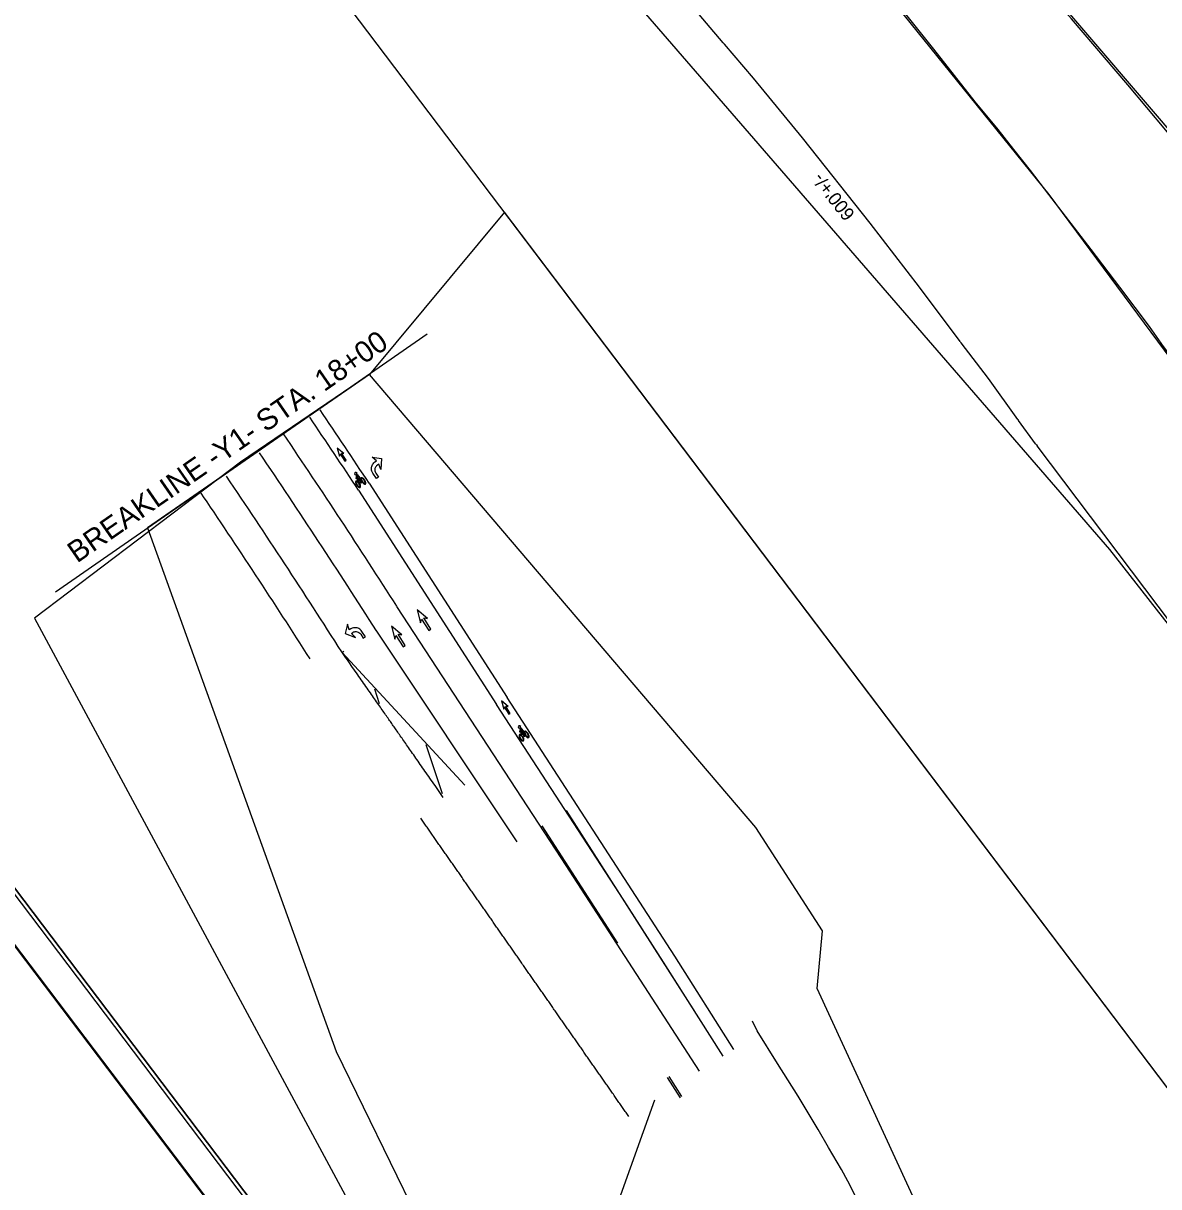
# Model space of a CAD drawing. Extents: x 2046295 to 2051060, y 758814 to 763808.
# Drawn here: x 2046525.7 to 2046973.6, y 759223.6 to 759682.5 of the extents above; entities that cross this region are included whole.
import ezdxf

# ---------------------------------------------------------------- set-up
doc = ezdxf.new("R2010")
doc.units = 0
for name, color, linetype in [('Default', 7, 'Continuous'), ('Exist Mkg 3ft Min Skp 9ft White', 7, 'Continuous'), ('Exist Mkg Skp Wht', 7, 'Continuous'), ('Exist Mkg Solid Double Yellow', 7, 'Continuous'), ('Exist Mkg Solid White Lane Line', 7, 'Continuous'), ('Exist Mkg Solid Yellow Diagonals', 7, 'Continuous'), ('Matchline', 7, 'Continuous'), ('Matchline Text', 7, 'Continuous'), ('Prop Conc 1ft 6in Curb and Gutter', 7, 'Continuous'), ('Prop DSN Text', 7, 'Continuous'), ('Prop EOT', 7, 'Continuous'), ('Prop Lane Lines', 7, 'Continuous'), ('Scratch_Level_0', 7, 'Continuous'), ('Scratch_Level_3', 7, 'Continuous'), ('Sheet Block Revision CELL', 7, 'Continuous'), ('Sheet Clip Boundary CELL', 7, 'Continuous'), ('Sheet Cutting Line CELL', 7, 'Continuous'), ('Sheet Plan CELL', 7, 'Continuous'), ('Sheet Plot Border Inside CELL', 7, 'Continuous'), ('Sheet Plot Border Outside CELL', 7, 'Continuous')]:
    doc.layers.add(name, color=color, linetype=linetype)

msp = doc.modelspace()

# ---------------------------------------------------------------- linework, layer by layer
at = {"layer": 'Default'}
msp.add_line((2046651.81, 759434.8), (2046652, 759434.52), dxfattribs=at)
at = {"layer": 'Exist Mkg 3ft Min Skp 9ft White'}
msp.add_line((2046720.53, 759359.65), (2046664.94, 759443.16), dxfattribs=at)
at = {"layer": 'Exist Mkg Skp Wht'}
for p, q in [((2046656.48, 759504.48), (2046656.6, 759504.57)), ((2046656.48, 759504.48), (2046656.6, 759504.57)), ((2046657.09, 759502.93), (2046657.26, 759504.26)), ((2046657.26, 759502.67), (2046657.09, 759502.93)), ((2046657.26, 759504.26), (2046657.47, 759504.52)), ((2046657.45, 759504.04), (2046657.26, 759502.67)), ((2046657.28, 759505.03), (2046657.41, 759505.12)), ((2046657.28, 759505.03), (2046657.41, 759505.12)), ((2046658.11, 759503.17), (2046657.45, 759504.04)), ((2046657.47, 759504.52), (2046658.49, 759503.19)), ((2046657.56, 759502.32), (2046658.11, 759503.17)), ((2046658.29, 759503.01), (2046657.86, 759502.36)), ((2046658.79, 759501.09), (2046658.29, 759503.01)), ((2046658.49, 759503.19), (2046659.02, 759501.15)), ((2046657.48, 759500.4), (2046657.28, 759500.27)), ((2046657.48, 759500.4), (2046657.28, 759500.27)), ((2046658.17, 759501.74), (2046657.56, 759502.32)), ((2046657.86, 759502.36), (2046658.33, 759501.91)), ((2046658.35, 759501), (2046658.15, 759500.86)), ((2046658.35, 759501), (2046658.15, 759500.86)), ((2046658.33, 759501.91), (2046658.17, 759501.74)), ((2046659.02, 759501.15), (2046658.8, 759501.06)), ((2046659.5, 759501.77), (2046659.3, 759501.64)), ((2046659.5, 759501.77), (2046659.3, 759501.64)), ((2046660.38, 759502.37), (2046660.18, 759502.23)), ((2046660.38, 759502.37), (2046660.18, 759502.23)), ((2046721.03, 759404.57), (2046721.16, 759404.66)), ((2046721.03, 759404.57), (2046721.16, 759404.66)), ((2046721.6, 759403), (2046721.81, 759404.33)), ((2046721.76, 759402.74), (2046721.6, 759403)), ((2046721.99, 759404.1), (2046721.76, 759402.74)), ((2046721.81, 759404.33), (2046722.02, 759404.58)), ((2046721.85, 759405.1), (2046721.98, 759405.18)), ((2046721.85, 759405.1), (2046721.98, 759405.18)), ((2046722.63, 759403.22), (2046721.99, 759404.1)), ((2046722.02, 759404.58), (2046723, 759403.23)), ((2046722.05, 759402.38), (2046722.63, 759403.22)), ((2046722.64, 759401.79), (2046722.05, 759402.38)), ((2046722.8, 759403.06), (2046722.36, 759402.41)), ((2046722.36, 759402.41), (2046722.81, 759401.95)), ((2046722.81, 759401.95), (2046722.64, 759401.79)), ((2046723.25, 759401.11), (2046722.8, 759403.06)), ((2046723, 759403.23), (2046723.48, 759401.17)), ((2046723.98, 759401.78), (2046723.78, 759401.65)), ((2046723.98, 759401.78), (2046723.78, 759401.65)), ((2046724.87, 759402.35), (2046724.67, 759402.22)), ((2046724.87, 759402.35), (2046724.67, 759402.22)), ((2046721.92, 759400.47), (2046721.71, 759400.34)), ((2046721.92, 759400.47), (2046721.71, 759400.34)), ((2046722.81, 759401.04), (2046722.61, 759400.91)), ((2046722.81, 759401.04), (2046722.61, 759400.91)), ((2046723.48, 759401.17), (2046723.26, 759401.09))]:
    msp.add_line(p, q, dxfattribs=at)
for points in [[(2046650.5, 759511.7), (2046650.71, 759512.61), (2046652.62, 759509.8), (2046653.15, 759510.16), (2046651.24, 759512.97), (2046652.17, 759512.83), (2046649.52, 759514.94)], [(2046650.5, 759511.7), (2046650.71, 759512.61), (2046652.62, 759509.8), (2046653.15, 759510.16), (2046651.24, 759512.97), (2046652.17, 759512.83), (2046649.52, 759514.94)], [(2046665.84, 759503.51), (2046665.01, 759502.96), (2046663.58, 759505.11), (2046663.34, 759505.52), (2046663.19, 759505.86), (2046663.08, 759506.26), (2046663.04, 759506.63), (2046663.05, 759506.94), (2046663.1, 759507.37), (2046663.19, 759507.69), (2046663.31, 759508.05), (2046663.51, 759508.47), (2046663.7, 759508.74), (2046663.99, 759509.08), (2046664.43, 759509.47), (2046665.1, 759509.91), (2046663.31, 759511.42), (2046667.1, 759510.83), (2046666.8, 759506.44), (2046665.98, 759508.59), (2046665.42, 759508.22), (2046665.12, 759508), (2046664.88, 759507.73), (2046664.73, 759507.48), (2046664.55, 759507.12), (2046664.46, 759506.83), (2046664.42, 759506.41), (2046664.47, 759505.99), (2046664.56, 759505.59), (2046664.78, 759505.11)], [(2046665.84, 759503.51), (2046665.01, 759502.96), (2046663.58, 759505.11), (2046663.34, 759505.52), (2046663.19, 759505.86), (2046663.08, 759506.26), (2046663.04, 759506.63), (2046663.05, 759506.94), (2046663.1, 759507.37), (2046663.19, 759507.69), (2046663.31, 759508.05), (2046663.51, 759508.47), (2046663.7, 759508.74), (2046663.99, 759509.08), (2046664.43, 759509.47), (2046665.1, 759509.91), (2046663.31, 759511.42), (2046667.1, 759510.83), (2046666.8, 759506.44), (2046665.98, 759508.59), (2046665.42, 759508.22), (2046665.12, 759508), (2046664.88, 759507.73), (2046664.73, 759507.48), (2046664.55, 759507.12), (2046664.46, 759506.83), (2046664.42, 759506.41), (2046664.47, 759505.99), (2046664.56, 759505.59), (2046664.78, 759505.11)], [(2046682.47, 759446.07), (2046682.85, 759447.5), (2046685.71, 759443), (2046686.56, 759443.53), (2046683.69, 759448.03), (2046685.14, 759447.77), (2046681.08, 759451.21)], [(2046682.47, 759446.07), (2046682.85, 759447.5), (2046685.71, 759443), (2046686.56, 759443.53), (2046683.69, 759448.03), (2046685.14, 759447.77), (2046681.08, 759451.21)], [(2046659.86, 759439.92), (2046660.7, 759440.46), (2046659.31, 759442.64), (2046659.03, 759443.03), (2046658.79, 759443.3), (2046658.47, 759443.56), (2046658.14, 759443.75), (2046657.86, 759443.87), (2046657.45, 759444), (2046657.12, 759444.05), (2046656.74, 759444.09), (2046656.28, 759444.07), (2046655.94, 759444.01), (2046655.52, 759443.89), (2046654.98, 759443.64), (2046654.31, 759443.21), (2046653.66, 759445.46), (2046652.66, 759441.76), (2046656.79, 759440.24), (2046655.16, 759441.87), (2046655.72, 759442.23), (2046656.05, 759442.41), (2046656.39, 759442.52), (2046656.68, 759442.56), (2046657.08, 759442.57), (2046657.39, 759442.54), (2046657.79, 759442.4), (2046658.15, 759442.19), (2046658.47, 759441.94), (2046658.83, 759441.54)], [(2046659.86, 759439.92), (2046660.7, 759440.46), (2046659.31, 759442.64), (2046659.03, 759443.03), (2046658.79, 759443.3), (2046658.47, 759443.56), (2046658.14, 759443.75), (2046657.86, 759443.87), (2046657.45, 759444), (2046657.12, 759444.05), (2046656.74, 759444.08), (2046656.28, 759444.07), (2046655.94, 759444.01), (2046655.52, 759443.89), (2046654.98, 759443.64), (2046654.31, 759443.21), (2046653.66, 759445.46), (2046652.66, 759441.76), (2046656.79, 759440.24), (2046655.16, 759441.87), (2046655.72, 759442.23), (2046656.05, 759442.41), (2046656.39, 759442.52), (2046656.68, 759442.56), (2046657.08, 759442.57), (2046657.39, 759442.54), (2046657.79, 759442.4), (2046658.15, 759442.19), (2046658.47, 759441.94), (2046658.83, 759441.54)], [(2046672.35, 759439.62), (2046672.73, 759441.05), (2046675.59, 759436.55), (2046676.43, 759437.09), (2046673.57, 759441.59), (2046675.02, 759441.32), (2046670.95, 759444.76)], [(2046672.35, 759439.62), (2046672.73, 759441.05), (2046675.59, 759436.55), (2046676.43, 759437.09), (2046673.57, 759441.59), (2046675.02, 759441.32), (2046670.95, 759444.76)], [(2046715.25, 759411.95), (2046715.48, 759412.85), (2046717.31, 759409.99), (2046717.85, 759410.33), (2046716.02, 759413.2), (2046716.95, 759413.03), (2046714.35, 759415.22)], [(2046715.25, 759411.95), (2046715.48, 759412.85), (2046717.31, 759409.99), (2046717.85, 759410.33), (2046716.02, 759413.2), (2046716.95, 759413.03), (2046714.35, 759415.22)]]:
    msp.add_lwpolyline(points, close=True, dxfattribs=at)
msp.add_lwpolyline([(2046792.44, 759269.2), (2046738.15, 759353), (2046673.12, 759452.53)], dxfattribs=at)
for centre, radius, start, end in [((2044127.83, 757827.13), 3020, 32.56209, 34.10565), ((2046656.94, 759504.8), 0.563, 34.1222, 214.1222), ((2046656.94, 759504.8), 0.563, 34.1222, 214.1222), ((2046656.94, 759504.8), 0.41, 214.1222, 34.1222), ((2044127.83, 757827.13), 2980, 32.58167, 34.0989), ((2046721.5, 759404.88), 0.563, 32.5817, 212.5817), ((2046721.5, 759404.88), 0.563, 32.5817, 212.5817), ((2046721.5, 759404.88), 0.41, 212.5817, 32.5817)]:
    msp.add_arc(centre, radius, start, end, dxfattribs=at)
for centre, major_axis, ratio, start_param, end_param in [((2046659.84, 759502), (0.84, -1.24), 0.435841, 1.570796, 4.712389), ((2046659.84, 759502), (0.7, -1.04), 0.325967, 1.570796, 4.712389), ((2046657.82, 759500.63), (0.84, -1.24), 0.435841, 1.570796, 4.712389), ((2046657.82, 759500.63), (0.7, -1.04), 0.325967, 1.570796, 4.712389), ((2046657.82, 759500.63), (0.84, -1.24), 0.435841, 4.712389, 7.853982), ((2046657.82, 759500.63), (0.7, -1.04), 0.325967, 4.712389, 7.853982), ((2046659.84, 759502), (0.84, -1.24), 0.435841, 4.712389, 7.853982), ((2046659.84, 759502), (0.7, -1.04), 0.325967, 4.712389, 7.853982), ((2046722.26, 759400.69), (0.8, -1.26), 0.435841, 1.570796, 4.712389), ((2046722.26, 759400.69), (0.67, -1.05), 0.325967, 1.570796, 4.712389), ((2046724.32, 759402), (0.8, -1.26), 0.435841, 1.570796, 4.712389), ((2046724.32, 759402), (0.67, -1.05), 0.325967, 1.570796, 4.712389), ((2046724.32, 759402), (0.8, -1.26), 0.435841, 4.712389, 7.853982), ((2046724.32, 759402), (0.67, -1.05), 0.325967, 4.712389, 7.853982), ((2046722.26, 759400.69), (0.8, -1.26), 0.435841, 4.712389, 7.853982), ((2046722.26, 759400.69), (0.67, -1.05), 0.325967, 4.712389, 7.853982)]:
    msp.add_ellipse(centre, major_axis=major_axis, ratio=ratio, start_param=start_param, end_param=end_param, dxfattribs=at)
for points in [[(2046723.55, 759310.15), (2046722.99, 759310.95), (2046722.44, 759311.74), (2046721.88, 759312.54), (2046721.33, 759313.33), (2046720.78, 759314.13), (2046720.22, 759314.92), (2046719.67, 759315.72), (2046719.11, 759316.51), (2046718.56, 759317.31), (2046718, 759318.1), (2046717.45, 759318.9), (2046716.89, 759319.69), (2046716.34, 759320.49), (2046715.78, 759321.28), (2046715.23, 759322.08), (2046714.67, 759322.87), (2046714.12, 759323.67), (2046713.56, 759324.46), (2046713.01, 759325.26), (2046712.46, 759326.05), (2046711.9, 759326.85), (2046711.35, 759327.64), (2046710.79, 759328.44), (2046710.24, 759329.23), (2046709.68, 759330.03), (2046709.13, 759330.82), (2046708.57, 759331.62), (2046708.02, 759332.41), (2046707.46, 759333.21), (2046706.91, 759334), (2046706.35, 759334.8), (2046705.8, 759335.59), (2046705.24, 759336.39), (2046704.69, 759337.18), (2046704.13, 759337.97), (2046703.58, 759338.77), (2046703.03, 759339.56), (2046702.47, 759340.36), (2046701.92, 759341.15), (2046701.36, 759341.95), (2046700.81, 759342.74), (2046700.25, 759343.54), (2046699.7, 759344.33), (2046699.14, 759345.13), (2046698.59, 759345.92), (2046698.03, 759346.72), (2046697.48, 759347.51), (2046696.92, 759348.31), (2046696.37, 759349.1), (2046695.81, 759349.9), (2046695.26, 759350.69), (2046694.7, 759351.49), (2046694.15, 759352.28), (2046693.6, 759353.08), (2046693.04, 759353.87), (2046692.49, 759354.67), (2046691.93, 759355.46), (2046691.38, 759356.26), (2046690.82, 759357.05), (2046690.27, 759357.85), (2046689.71, 759358.64), (2046689.16, 759359.44), (2046688.6, 759360.23), (2046688.05, 759361.03), (2046687.49, 759361.82), (2046686.94, 759362.62), (2046686.38, 759363.41), (2046685.83, 759364.21), (2046685.28, 759365), (2046684.72, 759365.8), (2046684.17, 759366.59), (2046683.61, 759367.38), (2046683.06, 759368.18), (2046682.5, 759368.97)], [(2046764.6, 759251.34), (2046764.04, 759252.13), (2046763.49, 759252.93), (2046762.93, 759253.72), (2046762.38, 759254.51), (2046761.82, 759255.31), (2046761.27, 759256.1), (2046760.71, 759256.9), (2046760.16, 759257.69), (2046759.6, 759258.49), (2046759.05, 759259.28), (2046758.49, 759260.08), (2046757.94, 759260.87), (2046757.38, 759261.67), (2046756.83, 759262.46), (2046756.28, 759263.26), (2046755.72, 759264.05), (2046755.17, 759264.85), (2046754.61, 759265.64), (2046754.06, 759266.44), (2046753.5, 759267.23), (2046752.95, 759268.03), (2046752.39, 759268.82), (2046751.84, 759269.62), (2046751.28, 759270.41), (2046750.73, 759271.21), (2046750.17, 759272), (2046749.62, 759272.8), (2046749.06, 759273.59), (2046748.51, 759274.39), (2046747.96, 759275.18), (2046747.4, 759275.98), (2046746.85, 759276.77), (2046746.29, 759277.57), (2046745.74, 759278.36), (2046745.18, 759279.16), (2046744.63, 759279.95), (2046744.07, 759280.75), (2046743.52, 759281.54), (2046742.96, 759282.33), (2046742.41, 759283.13), (2046741.85, 759283.92), (2046741.3, 759284.72), (2046740.74, 759285.51), (2046740.19, 759286.31), (2046739.63, 759287.1), (2046739.08, 759287.9), (2046738.53, 759288.69), (2046737.97, 759289.49), (2046737.42, 759290.28), (2046736.86, 759291.08), (2046736.31, 759291.87), (2046735.75, 759292.67), (2046735.2, 759293.46), (2046734.64, 759294.26), (2046734.09, 759295.05), (2046733.53, 759295.85), (2046732.98, 759296.64), (2046732.42, 759297.44), (2046731.87, 759298.23), (2046731.31, 759299.03), (2046730.76, 759299.82), (2046730.21, 759300.62), (2046729.65, 759301.41), (2046729.1, 759302.21), (2046728.54, 759303), (2046727.99, 759303.8), (2046727.43, 759304.59), (2046726.88, 759305.39), (2046726.32, 759306.18), (2046725.77, 759306.98), (2046725.21, 759307.77), (2046724.66, 759308.57), (2046724.1, 759309.36), (2046723.55, 759310.15)]]:
    msp.add_spline(points, degree=3, dxfattribs=at)
at = {"layer": 'Exist Mkg Solid Double Yellow'}
msp.add_line((2046651.57, 759434.26), (2046699.87, 759382), dxfattribs=at)
msp.add_arc((2044127.83, 757827.13), 2992, 32.49551, 34.08287, dxfattribs=at)
msp.add_open_spline([(2046691.41, 759377.18), (2046678.07, 759396.3), (2046664.73, 759415.41), (2046651.39, 759434.53)], degree=2, dxfattribs=at)
at = {"layer": 'Exist Mkg Solid White Lane Line'}
for p, q in [((2046657.96, 759498.37), (2046712.41, 759413.82)), ((2046662.17, 759501.08), (2046716.62, 759416.52)), ((2046782.69, 759314.52), (2046716.62, 759416.52)), ((2046762.66, 759336.67), (2046712.41, 759413.82)), ((2046778.28, 759312.14), (2046762.66, 759336.67)), ((2046806.06, 759277.82), (2046782.69, 759314.52)), ((2046801.84, 759275.13), (2046778.28, 759312.14))]:
    msp.add_line(p, q, dxfattribs=at)
for centre, radius, start, end in [((2044127.83, 757827.13), 3032.26, 33.4452, 34.10022), ((2044128.05, 757827.27), 3037, 33.44513, 34.10223), ((2044127.83, 757827.13), 3008, 32.48925, 34.08983)]:
    msp.add_arc(centre, radius, start, end, dxfattribs=at)
at = {"layer": 'Exist Mkg Solid Yellow Diagonals'}
for p, q in [((2046666.25, 759414.12), (2046664.35, 759419.84)), ((2046691.08, 759378.6), (2046684.63, 759397.94))]:
    msp.add_line(p, q, dxfattribs=at)
at = {"layer": 'Matchline'}
msp.add_line((2046538.46, 759458.31), (2046685.09, 759559.98), dxfattribs=at)
at = {"layer": 'Prop Conc 1ft 6in Curb and Gutter'}
msp.add_line((2046784.97, 759258.73), (2046779.83, 759266.73), dxfattribs=at)
at = {"layer": 'Prop DSN Text'}
for p, q in [((2046925.05, 759516.62), (2046918.33, 759525.83)), ((2047001.09, 759415.7), (2046925.61, 759515.87))]:
    msp.add_line(p, q, dxfattribs=at)
for points in [[(2046801.8, 759674.76), (2046780.7, 759699.83), (2046762.53, 759720.33), (2046746.64, 759737.54), (2046726.23, 759758.63), (2046693.13, 759791.87)], [(2046895.26, 759556.98), (2046879.26, 759578.34), (2046859.74, 759603.68), (2046833.08, 759637.27), (2046813.8, 759660.86), (2046802.29, 759674.18)], [(2046918.09, 759526.16), (2046906.41, 759542.41), (2046895.64, 759556.47)], [(2046774.7, 759257.74), (2046728.05, 759127.34), (2046781.19, 759057.15)]]:
    msp.add_lwpolyline(points, dxfattribs=at)
for centre, start, end in [((2046848.13, 759713.76), 220.084, 220.8093), ((2046943.74, 759593.28), 216.8291, 217.4304), ((2046967.26, 759561.52), 215.7218, 216.1123), ((2046973.98, 759552.32), 216.1123, 217.0013)]:
    msp.add_arc(centre, 60.56, start, end, dxfattribs=at)
at = {"layer": 'Prop EOT'}
msp.add_line((2046785.53, 759259.25), (2046780.45, 759267.14), dxfattribs=at)
for points in [[(2047095.91, 759487.83), (2047060.1, 759534.55), (2047037.66, 759563.83), (2047019.89, 759587.02), (2047003.2, 759607.99), (2046976.38, 759640.27), (2046961.44, 759658.24), (2046939.14, 759684.21), (2046899.4, 759728.85), (2046871.69, 759758.79), (2046844.06, 759788.42), (2046836.53, 759796.51), (2046823.09, 759810.56), (2046805.62, 759829.99), (2046780.45, 759856.59), (2046770.6, 759867.45), (2046758.76, 759880.49), (2046748.01, 759892.54), (2046735.95, 759905.24)], [(2047051.48, 759453.65), (2047026.19, 759487.57), (2047004.02, 759517.31), (2046975.49, 759555.05), (2046969.9, 759562.91), (2046958.31, 759578.45), (2046946.96, 759593.22), (2046930.3, 759614.91), (2046923.02, 759624.38), (2046916.39, 759632.65), (2046910.23, 759640.6), (2046901.22, 759651.47), (2046884.87, 759672.25), (2046869.65, 759691.35), (2046862.8, 759699.47), (2046849.9, 759714.08), (2046843.12, 759722.39), (2046829.52, 759739.07)], [(2046902.81, 759078.93), (2046899.13, 759090.75), (2046894.62, 759105.13), (2046890.16, 759119.62), (2046885.7, 759134.17), (2046881.06, 759148.64), (2046875.97, 759162.93), (2046870.62, 759177.24), (2046865.21, 759191.44), (2046859.85, 759205.62), (2046853.99, 759219.94), (2046850.92, 759225.87), (2046848.49, 759230.47), (2046843.38, 759239.17), (2046839.32, 759246.17), (2046831.35, 759259.3), (2046823.26, 759272.18), (2046815.25, 759285.09), (2046813.33, 759288.92)]]:
    msp.add_lwpolyline(points, dxfattribs=at)
at = {"layer": 'Prop Lane Lines'}
for p, q in [((2046739.83, 759372.07), (2046790.82, 759292.32)), ((2046730.32, 759365.94), (2046760.07, 759319.7))]:
    msp.add_line(p, q, dxfattribs=at)
at = {"layer": 'Scratch_Level_0'}
for points in [[(2047115.74, 759268.55), (2046954.25, 759474.97), (2046742.37, 759719.71), (2046585.96, 759952.37), (2046640.17, 759899.32), (2046664.8, 759908.52), (2046703.35, 759870.04), (2046780.77, 759790.76), (2046816.65, 759751.71), (2046851.83, 759710.23), (2046854.21, 759708.09), (2046873.14, 759685.6), (2046930.3, 759614.91), (2047005.4, 759513.5)], [(2046984.79, 759632.17), (2046929.97, 759696.38), (2046746.39, 759895.6), (2046735.95, 759905.24), (2046715.87, 759927.6), (2046843.22, 759930.29), (2047114.24, 759559.33)]]:
    msp.add_lwpolyline(points, dxfattribs=at)
for points in [[(2046861, 759015.21), (2046855.71, 759033.09), (2046907.33, 759050.49), (2046914.93, 759030.03), (2046958.13, 759043.02), (2046838.92, 759301.79), (2046841.01, 759324.58), (2046814.68, 759365.26), (2046662.34, 759543.92), (2046574.76, 759483.48), (2046649.15, 759276.93), (2046691.7, 759189.63), (2046847.81, 759009.86)], [(2046861, 759015.21), (2046868.18, 759017.8), (2046909.83, 759028.44), (2046914.93, 759030.03), (2046958.13, 759043.02), (2046838.92, 759301.79), (2046841.01, 759324.58), (2046814.68, 759365.26), (2046662.34, 759543.92), (2046574.76, 759483.48), (2046649.15, 759276.93), (2046691.7, 759189.63), (2046847.81, 759009.86)]]:
    msp.add_lwpolyline(points, close=True, dxfattribs=at)
at = {"layer": 'Scratch_Level_3'}
msp.add_lwpolyline([(2046611.43, 759509.41), (2046530.13, 759447.86), (2046668.42, 759191.21), (2046850.67, 758939.32), (2046974.7, 759016.31), (2047093.77, 759108.41), (2046789, 759510.96), (2046715.54, 759607.98), (2046662.34, 759543.92)], close=True, dxfattribs=at)
at = {"layer": 'Sheet Block Revision CELL'}
msp.add_line((2047106.56, 759091.51), (2046563.3, 759809.07), dxfattribs=at)
at = {"layer": 'Sheet Clip Boundary CELL'}
msp.add_lwpolyline([(2046947.67, 758972.8), (2047186.85, 759153.88), (2047203.68, 759209.07), (2047315.83, 759293.98), (2046807.51, 759978.36), (2046429.78, 759650.86), (2046498.33, 759560.32), (2046397.16, 759483.72), (2046835.66, 758904.54)], close=True, dxfattribs=at)
at = {"layer": 'Sheet Cutting Line CELL'}
msp.add_line((2046295.24, 759618.91), (2046904.95, 758813.59), dxfattribs=at)
at = {"layer": 'Sheet Plan CELL'}
for points in [[(2046312.14, 759618.94), (2046855.41, 758901.37), (2047357.69, 759281.65), (2046814.43, 759999.2)], [(2047357.69, 759281.65), (2046855.43, 758901.37), (2046384.6, 759523.22), (2046456.38, 759577.58), (2046383.94, 759673.27), (2046814.43, 759999.2)]]:
    msp.add_lwpolyline(points, close=True, dxfattribs=at)
at = {"layer": 'Sheet Plot Border Inside CELL'}
msp.add_lwpolyline([(2047414.48, 759209.14), (2046811.11, 760006.08), (2046306.43, 759624), (2046909.81, 758827.05)], close=True, dxfattribs=at)
at = {"layer": 'Sheet Plot Border Outside CELL'}
msp.add_lwpolyline([(2047428.76, 759210.16), (2046819.05, 760015.49), (2046295.24, 759618.91), (2046904.95, 758813.59)], close=True, dxfattribs=at)

# ---------------------------------------------------------------- texts
at = {"layer": 'Matchline Text'}
msp.add_text('BREAKLINE -Y1- STA. 18+00', height=8.4, rotation=34.7338, dxfattribs=at).set_placement((2046546.96, 759469.39))
at = {"layer": 'Prop DSN Text'}
msp.add_text("600'+/-", height=5.25, rotation=128.6491, dxfattribs=at).set_placement((2046854.03, 759607.28))

doc.saveas('drawing.dxf')
